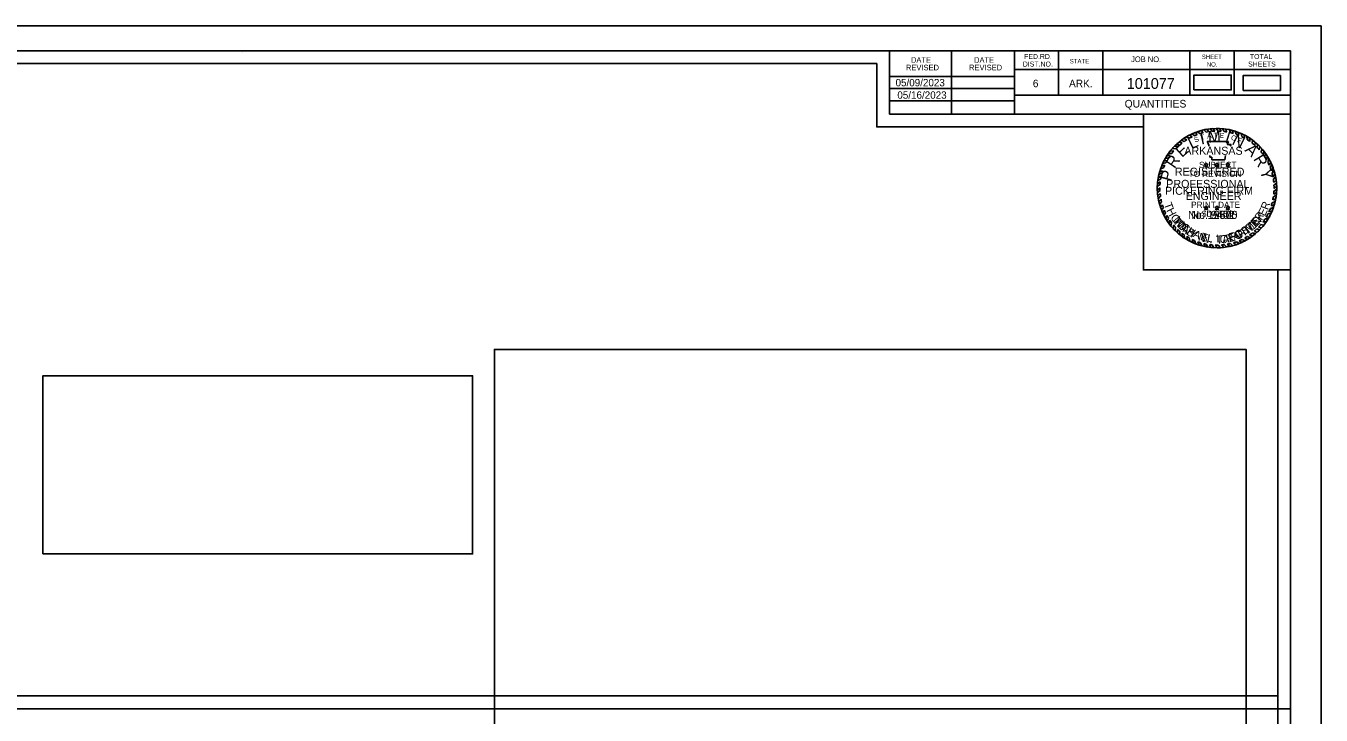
# Model space of a CAD drawing. Extents: x 1369655 to 1370989, y 380216 to 380430.
# Drawn here: x 1370286.3 to 1370488.6, y 380322.1 to 380429.8 of the extents above; entities that cross this region are included whole.
import ezdxf

# ---------------------------------------------------------------- set-up
doc = ezdxf.new("R2010")
doc.units = 0
for name, color, linetype in [('Default', 7, 'Continuous'), ('R_Border', 7, 'Continuous'), ('R_Border Notes', 7, 'Continuous'), ('R_Border Plan-Plan', 7, 'Continuous'), ('R_No Plot', 7, 'Continuous'), ('R_Revision Date Text', 7, 'Continuous'), ('STAMP_PE_CRAFTON', 7, 'Continuous'), ('STAMP_PE_FOSTER', 7, 'Continuous'), ('STAMP_PE_SEAL-INFO', 7, 'Continuous'), ('STAMP_PE_TAEGTMEYER', 7, 'Continuous'), ('STAMP_PE_TXT', 7, 'Continuous'), ('STAMP_PRELIMINARY', 7, 'Continuous')]:
    doc.layers.add(name, color=color, linetype=linetype)

msp = doc.modelspace()

# ---------------------------------------------------------------- linework, layer by layer
at = {"layer": 'Default'}
for points in [[(1370468.73, 380419.77), (1370474.56, 380419.77), (1370474.56, 380422.08), (1370468.73, 380422.08)], [(1370476.41, 380419.69), (1370482.24, 380419.69), (1370482.24, 380422), (1370476.41, 380422)], [(1370359.47, 380256.61), (1370476.87, 380256.61), (1370476.87, 380379.23), (1370359.47, 380379.23)], [(1370288.98, 380347.31), (1370356.07, 380347.31), (1370356.07, 380375.14), (1370288.98, 380375.14)]]:
    msp.add_lwpolyline(points, close=True, dxfattribs=at)
at = {"layer": 'R_Border'}
for p, q in [((1370167.65, 380425.87), (1370483.83, 380425.87)), ((1370320.17, 380425.61), (1370320.17, 380425.61)), ((1370320.17, 380425.61), (1370320.17, 380425.61)), ((1370421.19, 380415.99), (1370421.19, 380425.87)), ((1370430.87, 380415.99), (1370430.87, 380425.87)), ((1370440.73, 380425.87), (1370440.73, 380415.99)), ((1370447.57, 380425.87), (1370447.57, 380418.93)), ((1370454.51, 380425.87), (1370454.51, 380418.93)), ((1370468.09, 380425.87), (1370468.09, 380418.93)), ((1370475.03, 380425.87), (1370475.03, 380418.93)), ((1370483.83, 380220.41), (1370483.83, 380425.87)), ((1370421.19, 380421.85), (1370440.73, 380421.85)), ((1370483.83, 380422.93), (1370440.73, 380422.93)), ((1370483.83, 380422.95), (1370483.83, 380422.95)), ((1370421.19, 380419.99), (1370440.73, 380419.99)), ((1370421.19, 380418.05), (1370440.73, 380418.05)), ((1370483.83, 380418.93), (1370440.73, 380418.93)), ((1370443.69, 380418.93), (1370483.83, 380418.93)), ((1370483.83, 380415.99), (1370421.19, 380415.99))]:
    msp.add_line(p, q, dxfattribs=at)
at = {"layer": 'R_Border Plan-Plan'}
msp.add_line((1370167.65, 380323.14), (1370483.83, 380323.14), dxfattribs=at)
at = {"layer": 'R_No Plot'}
for points in [[(1370155.25, 380429.76), (1370488.59, 380429.76), (1370488.59, 380216.42), (1370155.25, 380216.42)], [(1370481.83, 380325.14), (1370169.65, 380325.14), (1370169.65, 380423.87), (1370419.19, 380423.87), (1370419.19, 380413.99), (1370436.73, 380413.99), (1370460.83, 380413.99), (1370460.83, 380391.65), (1370481.83, 380391.65)], [(1370169.65, 380423.87), (1370419.19, 380423.87), (1370419.19, 380413.99), (1370436.73, 380413.99), (1370460.83, 380413.99), (1370460.83, 380391.65), (1370481.83, 380391.65), (1370481.83, 380222.41), (1370169.65, 380222.41)], [(1370460.83, 380415.99), (1370483.83, 380415.99), (1370483.83, 380391.65), (1370460.83, 380391.65)]]:
    msp.add_lwpolyline(points, close=True, dxfattribs=at)
at = {"layer": 'STAMP_PE_SEAL-INFO'}
for p, q in [((1370468.95, 380413.12), (1370469.24, 380412.79)), ((1370469.29, 380413.24), (1370469.67, 380412.94)), ((1370469.88, 380413.43), (1370470.17, 380413.08)), ((1370470.27, 380413.52), (1370470.63, 380413.18)), ((1370470.75, 380413.62), (1370471.05, 380413.25)), ((1370471.27, 380413.69), (1370471.55, 380413.31)), ((1370472.01, 380413.34), (1370471.69, 380413.73)), ((1370472.5, 380413.34), (1370472.22, 380413.75)), ((1370472.96, 380413.32), (1370472.7, 380413.75)), ((1370473.47, 380413.27), (1370473.18, 380413.71)), ((1370473.89, 380413.21), (1370473.64, 380413.66)), ((1370474.46, 380413.09), (1370474.28, 380413.55)), ((1370474.86, 380412.98), (1370474.7, 380413.45)), ((1370475.31, 380412.83), (1370475.17, 380413.31)), ((1370475.73, 380412.67), (1370475.58, 380413.17)), ((1370466.03, 380411.3), (1370466.49, 380411.16)), ((1370466.37, 380411.6), (1370466.9, 380411.5)), ((1370466.75, 380411.93), (1370467.21, 380411.72)), ((1370467.17, 380412.19), (1370467.61, 380411.99)), ((1370467.56, 380412.44), (1370467.99, 380412.21)), ((1370468.01, 380412.69), (1370468.47, 380412.46)), ((1370468.44, 380412.9), (1370468.83, 380412.62)), ((1370470.81, 380411.72), (1370474.15, 380411.72)), ((1370470.93, 380411.41), (1370470.81, 380411.72)), ((1370471.03, 380411.12), (1370470.93, 380411.41)), ((1370471.04, 380411), (1370471.03, 380411.12)), ((1370474.15, 380411.72), (1370473.93, 380411.23)), ((1370473.93, 380411.23), (1370474.56, 380411.23)), ((1370474.56, 380411.23), (1370474.41, 380411)), ((1370476.19, 380412.47), (1370476.09, 380412.96)), ((1370476.63, 380412.24), (1370476.55, 380412.75)), ((1370477.02, 380412.01), (1370476.98, 380412.51)), ((1370477.46, 380411.72), (1370477.42, 380412.24)), ((1370477.82, 380411.46), (1370477.85, 380411.94)), ((1370478.26, 380411.09), (1370478.28, 380411.61)), ((1370478.58, 380410.79), (1370478.65, 380411.29)), ((1370464.27, 380409.11), (1370464.76, 380409.13)), ((1370464.51, 380409.51), (1370465.03, 380409.54)), ((1370464.75, 380409.85), (1370465.25, 380409.85)), ((1370465.03, 380410.22), (1370465.58, 380410.24)), ((1370465.37, 380410.63), (1370465.89, 380410.59)), ((1370465.7, 380410.98), (1370466.24, 380410.93)), ((1370471.23, 380409.29), (1370471.2, 380409.51)), ((1370471.54, 380409.29), (1370471.23, 380409.29)), ((1370471.54, 380408.86), (1370471.54, 380409.29)), ((1370473.59, 380409.2), (1370473.57, 380408.86)), ((1370473.67, 380409.51), (1370473.59, 380409.2)), ((1370478.93, 380410.42), (1370479, 380410.95)), ((1370479.21, 380410.1), (1370479.35, 380410.57)), ((1370479.53, 380409.69), (1370479.67, 380410.19)), ((1370479.75, 380409.37), (1370479.93, 380409.83)), ((1370480.06, 380408.87), (1370480.24, 380409.36)), ((1370463.36, 380406.95), (1370463.84, 380407.12)), ((1370463.52, 380407.45), (1370464, 380407.59)), ((1370463.67, 380407.86), (1370464.17, 380408.01)), ((1370463.85, 380408.29), (1370464.35, 380408.4)), ((1370464.04, 380408.68), (1370464.54, 380408.75)), ((1370473.57, 380408.86), (1370471.54, 380408.86)), ((1370480.26, 380408.51), (1370480.49, 380408.95)), ((1370480.49, 380408.02), (1370480.72, 380408.51)), ((1370480.63, 380407.69), (1370480.9, 380408.12)), ((1370480.83, 380407.14), (1370481.1, 380407.61)), ((1370480.93, 380406.77), (1370481.23, 380407.22)), ((1370463.44, 380404.98), (1370463.02, 380404.72)), ((1370463.47, 380405.4), (1370463.04, 380405.12)), ((1370463.53, 380405.84), (1370463.09, 380405.62)), ((1370463.62, 380406.3), (1370463.15, 380406.05)), ((1370463.25, 380406.54), (1370463.72, 380406.74)), ((1370481.07, 380406.21), (1370481.39, 380406.66)), ((1370481.14, 380405.83), (1370481.49, 380406.19)), ((1370481.2, 380405.32), (1370481.57, 380405.66)), ((1370481.23, 380404.91), (1370481.62, 380405.2)), ((1370463.42, 380404.49), (1370463.02, 380404.15)), ((1370463.43, 380404.08), (1370463.04, 380403.75)), ((1370463.46, 380403.58), (1370463.09, 380403.23)), ((1370463.51, 380403.15), (1370463.16, 380402.78)), ((1370481.15, 380403.09), (1370481.59, 380403.31)), ((1370481.2, 380403.48), (1370481.63, 380403.73)), ((1370481.24, 380403.98), (1370481.66, 380404.26)), ((1370481.25, 380404.39), (1370481.65, 380404.71)), ((1370463.59, 380402.69), (1370463.25, 380402.33)), ((1370463.68, 380402.28), (1370463.37, 380401.86)), ((1370463.81, 380401.83), (1370463.51, 380401.41)), ((1370463.95, 380401.41), (1370463.67, 380400.99)), ((1370464.12, 380400.98), (1370463.85, 380400.56)), ((1370480.67, 380401.26), (1370481.15, 380401.39)), ((1370480.8, 380401.64), (1370481.29, 380401.84)), ((1370480.95, 380402.14), (1370481.42, 380402.34)), ((1370481.06, 380402.59), (1370481.51, 380402.78)), ((1370464.29, 380400.6), (1370464.06, 380400.13)), ((1370464.52, 380400.14), (1370464.33, 380399.65)), ((1370464.76, 380399.73), (1370464.57, 380399.26)), ((1370464.96, 380399.42), (1370464.85, 380398.87)), ((1370465.24, 380399.03), (1370465.14, 380398.5)), ((1370479.51, 380399.14), (1370480.01, 380399.14)), ((1370479.85, 380399.63), (1370480.32, 380399.63)), ((1370480.02, 380399.91), (1370480.52, 380399.97)), ((1370480.29, 380400.41), (1370480.78, 380400.48)), ((1370480.45, 380400.75), (1370480.94, 380400.84)), ((1370465.54, 380398.65), (1370465.46, 380398.13)), ((1370465.85, 380398.32), (1370465.79, 380397.79)), ((1370466.17, 380397.99), (1370466.14, 380397.46)), ((1370466.51, 380397.68), (1370466.51, 380397.15)), ((1370466.87, 380397.38), (1370466.89, 380396.86)), ((1370467.21, 380397.13), (1370467.25, 380396.62)), ((1370477.08, 380396.89), (1370477.53, 380396.69)), ((1370477.42, 380397.11), (1370477.86, 380396.92)), ((1370477.88, 380397.46), (1370478.35, 380397.31)), ((1370478.16, 380397.68), (1370478.63, 380397.55)), ((1370478.56, 380398.05), (1370479, 380397.91)), ((1370478.82, 380398.31), (1370479.29, 380398.23)), ((1370479.2, 380398.74), (1370479.66, 380398.67)), ((1370467.64, 380396.85), (1370467.7, 380396.34)), ((1370467.99, 380396.65), (1370468.08, 380396.13)), ((1370468.47, 380396.4), (1370468.63, 380395.88)), ((1370468.84, 380396.23), (1370469.02, 380395.72)), ((1370469.34, 380396.04), (1370469.55, 380395.53)), ((1370469.75, 380395.9), (1370469.97, 380395.41)), ((1370470.25, 380395.76), (1370470.47, 380395.3)), ((1370470.65, 380395.68), (1370470.9, 380395.22)), ((1370471.15, 380395.6), (1370471.39, 380395.16)), ((1370471.59, 380395.55), (1370471.86, 380395.12)), ((1370472.07, 380395.52), (1370472.38, 380395.11)), ((1370472.53, 380395.52), (1370472.88, 380395.12)), ((1370473.05, 380395.55), (1370473.38, 380395.17)), ((1370473.49, 380395.59), (1370473.86, 380395.23)), ((1370473.93, 380395.66), (1370474.32, 380395.32)), ((1370474.43, 380395.77), (1370474.8, 380395.44)), ((1370474.89, 380395.89), (1370475.3, 380395.59)), ((1370475.38, 380396.05), (1370475.82, 380395.78)), ((1370475.8, 380396.22), (1370476.22, 380395.96)), ((1370476.26, 380396.43), (1370476.74, 380396.22)), ((1370476.67, 380396.64), (1370477.08, 380396.41))]:
    msp.add_line(p, q, dxfattribs=at)
for radius, start, end in [(9.32, 111.3124, 114.7026), (9.32, 105.2339, 109.0352), (8.91, 104.0352, 107.3615), (9.32, 99.7525, 102.7765), (8.91, 98.258, 101.0329), (9.32, 93.9381, 96.5517), (8.91, 92.1102, 95.0367), (9.32, 87.7298, 90.6707), (8.91, 85.9628, 88.9097), (9.32, 81.9732, 84.8236), (8.91, 79.9264, 82.696), (9.32, 75.3125, 77.9426), (8.91, 73.5575, 76.2314), (9.32, 69.6061, 72.3058), (9.32, 129.7326, 132.5376), (8.91, 127.5297, 130.9683), (9.32, 123.6199, 126.5906), (8.91, 121.9746, 125.11), (9.32, 117.6544, 120.8099), (8.91, 115.6869, 119.1583), (8.91, 110.3086, 113.1659), (8.91, 67.6248, 70.504), (9.32, 63.1329, 66.2704), (8.91, 61.1558, 64.3784), (9.32, 56.9003, 60.0942), (8.91, 54.9238, 58.2702), (8.91, 48.3016, 52.0395), (9.32, 50.3492, 53.7159), (9.32, 44.3405, 47.3929), (9.32, 147.0072, 149.899), (9.32, 141.6056, 144.4486), (8.91, 145.0197, 148.2104), (8.91, 139.301, 142.5873), (9.32, 135.4021, 138.3031), (8.91, 133.1331, 136.2562), (8.91, 42.2212, 45.5512), (8.91, 36.135, 39.5311), (9.32, 38.1247, 41.2316), (8.91, 29.9032, 33.6645), (9.32, 31.9614, 35.4294), (9.32, 158.4077, 161.0701), (8.91, 162.4331, 165.0013), (9.32, 152.864, 155.5189), (8.91, 156.3402, 159.2319), (8.91, 151.0315, 153.573), (8.91, 23.7732, 27.2211), (9.32, 25.9391, 29.0125), (8.91, 17.6802, 21.4251), (9.32, 19.9538, 23.3141), (9.32, 13.8421, 17.4447), (9.32, 175.7409, 178.2066), (9.32, 170.0003, 172.6878), (9.32, 164.3068, 166.894), (8.91, 173.73, 176.4734), (8.91, 167.9048, 170.9039), (8.91, 11.5444, 15.2364), (8.91, 5.7599, 9.0606), (9.32, 7.5852, 10.8621), (9.32, 1.7215, 4.7268), (9.32, 181.7251, 184.1626), (9.32, 187.4204, 190.1927), (8.91, 179.6454, 182.2633), (8.91, 185.4539, 188.234), (8.91, 348.0778, 351.3435), (8.91, 353.8632, 357.1274), (8.91, 359.7329, 3.0639), (9.32, 349.8305, 353.0885), (9.32, 355.7156, 358.9569), (9.32, 193.0369, 195.9973), (9.32, 198.8967, 201.6281), (8.91, 191.2274, 193.9858), (8.91, 196.9675, 199.8353), (8.91, 202.7761, 205.4791), (8.91, 335.6038, 339.1858), (8.91, 341.777, 345.0925), (9.32, 337.3837, 340.9933), (9.32, 343.8925, 347.035), (9.32, 204.5479, 207.4328), (9.32, 210.8636, 213.6571), (8.91, 208.7883, 211.7934), (8.91, 214.1838, 217.2747), (8.91, 323.5851, 327.4407), (9.32, 325.4405, 328.9872), (8.91, 329.5549, 333.2076), (9.32, 331.4037, 334.9332), (9.32, 216.6115, 219.491), (9.32, 222.48, 225.3801), (8.91, 220.3909, 223.3056), (9.32, 228.3665, 231.348), (8.91, 226.2494, 229.2407), (8.91, 232.229, 234.9336), (8.91, 299.0768, 302.1724), (8.91, 304.823, 308.5143), (9.32, 306.3721, 310.208), (8.91, 310.7744, 314.3161), (9.32, 312.4518, 315.6633), (8.91, 316.6531, 320.3711), (9.32, 318.2846, 321.8043), (9.32, 234.295, 236.9452), (8.91, 238.2223, 240.8353), (9.32, 240.1977, 242.8613), (8.91, 244.3204, 246.9486), (9.32, 246.576, 249.1558), (8.91, 250.3491, 253.1216), (9.32, 252.5967, 255.3252), (8.91, 256.505, 259.1192), (9.32, 258.4433, 261.1398), (8.91, 262.3783, 265.2012), (9.32, 264.1978, 267.1009), (8.91, 268.3215, 271.277), (9.32, 270.2548, 273.3361), (8.91, 274.6157, 277.4486), (9.32, 276.4239, 279.4357), (8.91, 280.3459, 283.5814), (9.32, 282.3199, 285.3702), (8.91, 286.6423, 289.9783), (9.32, 288.5709, 291.9733), (8.91, 292.8745, 296.1185), (9.32, 294.6481, 298.2166), (9.32, 300.621, 303.8703)]:
    msp.add_arc((1370472.33, 380404.43), radius, start, end, dxfattribs=at)
at = {"layer": 'STAMP_PE_TXT'}
for p, q in [((1370470.51, 380408), (1370470.31, 380408.15)), ((1370470.31, 380408.15), (1370470.56, 380408.15)), ((1370470.44, 380407.77), (1370470.51, 380408)), ((1370470.64, 380407.91), (1370470.44, 380407.77)), ((1370470.56, 380408.15), (1370470.64, 380408.38)), ((1370470.64, 380408.38), (1370470.71, 380408.15)), ((1370470.83, 380407.77), (1370470.64, 380407.91)), ((1370470.71, 380408.15), (1370470.96, 380408.15)), ((1370470.96, 380408.15), (1370470.76, 380408)), ((1370470.76, 380408), (1370470.83, 380407.77)), ((1370472.21, 380408), (1370472.01, 380408.15)), ((1370472.01, 380408.15), (1370472.26, 380408.15)), ((1370472.14, 380407.77), (1370472.21, 380408)), ((1370472.33, 380407.91), (1370472.14, 380407.77)), ((1370472.26, 380408.15), (1370472.33, 380408.38)), ((1370472.33, 380408.38), (1370472.41, 380408.15)), ((1370472.53, 380407.77), (1370472.33, 380407.91)), ((1370472.41, 380408.15), (1370472.65, 380408.15)), ((1370472.65, 380408.15), (1370472.46, 380408)), ((1370472.46, 380408), (1370472.53, 380407.77)), ((1370473.91, 380408), (1370473.71, 380408.15)), ((1370473.71, 380408.15), (1370473.96, 380408.15)), ((1370473.83, 380407.77), (1370473.91, 380408)), ((1370474.03, 380407.91), (1370473.83, 380407.77)), ((1370473.96, 380408.15), (1370474.03, 380408.38)), ((1370474.03, 380408.38), (1370474.11, 380408.15)), ((1370474.23, 380407.77), (1370474.03, 380407.91)), ((1370474.11, 380408.15), (1370474.35, 380408.15)), ((1370474.35, 380408.15), (1370474.15, 380408)), ((1370474.15, 380408), (1370474.23, 380407.77)), ((1370470.51, 380401.29), (1370470.31, 380401.44)), ((1370470.31, 380401.44), (1370470.56, 380401.44)), ((1370470.44, 380401.06), (1370470.51, 380401.29)), ((1370470.64, 380401.21), (1370470.44, 380401.06)), ((1370470.56, 380401.44), (1370470.64, 380401.67)), ((1370470.64, 380401.67), (1370470.71, 380401.44)), ((1370470.83, 380401.06), (1370470.64, 380401.21)), ((1370470.71, 380401.44), (1370470.96, 380401.44)), ((1370470.96, 380401.44), (1370470.76, 380401.29)), ((1370470.76, 380401.29), (1370470.83, 380401.06)), ((1370472.21, 380401.29), (1370472.01, 380401.44)), ((1370472.01, 380401.44), (1370472.26, 380401.44)), ((1370472.14, 380401.06), (1370472.21, 380401.29)), ((1370472.33, 380401.21), (1370472.14, 380401.06)), ((1370472.26, 380401.44), (1370472.33, 380401.67)), ((1370472.33, 380401.67), (1370472.41, 380401.44)), ((1370472.53, 380401.06), (1370472.33, 380401.21)), ((1370472.41, 380401.44), (1370472.65, 380401.44)), ((1370472.65, 380401.44), (1370472.46, 380401.29)), ((1370472.46, 380401.29), (1370472.53, 380401.06)), ((1370473.91, 380401.29), (1370473.71, 380401.44)), ((1370473.71, 380401.44), (1370473.96, 380401.44)), ((1370473.83, 380401.06), (1370473.91, 380401.29)), ((1370474.03, 380401.21), (1370473.83, 380401.06)), ((1370473.96, 380401.44), (1370474.03, 380401.67)), ((1370474.03, 380401.67), (1370474.11, 380401.44)), ((1370474.23, 380401.06), (1370474.03, 380401.21)), ((1370474.11, 380401.44), (1370474.35, 380401.44)), ((1370474.35, 380401.44), (1370474.15, 380401.29)), ((1370474.15, 380401.29), (1370474.23, 380401.06))]:
    msp.add_line(p, q, dxfattribs=at)
at = {"layer": 'STAMP_PRELIMINARY'}
msp.add_circle((1370472.33, 380404.43), 9.32, dxfattribs=at)

# ---------------------------------------------------------------- texts
at = {"layer": 'R_Border'}
for s, height, p in [('FED.RD.', 0.782, (1370442.21, 380424.59)), ('SHEET', 0.684, (1370469.95, 380424.59)), ('TOTAL', 0.782, (1370477.47, 380424.59)), ('REVISED', 0.879, (1370423.75, 380422.82)), ('DATE', 0.879, (1370424.53, 380424)), ('REVISED', 0.879, (1370433.61, 380422.82)), ('DATE', 0.879, (1370434.39, 380424)), ('DIST.NO.', 0.782, (1370442.01, 380423.41)), ('STATE', 0.684, (1370449.33, 380423.91)), ('JOB NO.', 0.879, (1370458.91, 380424.11)), ('NO.', 0.684, (1370470.73, 380423.41)), ('SHEETS', 0.782, (1370477.19, 380423.41)), ('6', 1.17, (1370443.57, 380420.19)), ('ARK.', 1.172, (1370449.23, 380420.19))]:
    msp.add_text(s, height=height, dxfattribs=at).set_placement(p)
at = {"layer": 'R_Border Notes'}
for s, height, p in [('101077', 1.68, (1370458.24, 380419.93)), ('QUANTITIES', 1.2, (1370457.91, 380417.01))]:
    msp.add_text(s, height=height, dxfattribs=at).set_placement(p)
at = {"layer": 'R_Revision Date Text'}
for s, p in [('05/09/2023', (1370422.13, 380420.33)), ('05/16/2023', (1370422.41, 380418.39))]:
    msp.add_text(s, height=1.15, dxfattribs=at).set_placement(p)
at = {"layer": 'STAMP_PE_CRAFTON'}
for s, rotation, p in [('T', 310.7442, (1370465.3, 380399.33)), ('O', 317.6422, (1370465.97, 380398.52)), ('O', 41.8391, (1370477.77, 380397.67)), ('N', 49.2411, (1370478.62, 380398.45)), ('N', 324.4537, (1370466.81, 380397.73)), ('Y', 331.1686, (1370467.85, 380397.02)), ('N', 347.4752, (1370469.9, 380396.1)), ('C', 6.0117, (1370472.81, 380395.77)), ('R', 14.8189, (1370473.9, 380395.89)), ('A', 20.5125, (1370475.01, 380396.19)), ('F', 28.7821, (1370475.99, 380396.56)), ('T', 34.1136, (1370476.91, 380397.07)), ('.', 356.8926, (1370471.13, 380395.82))]:
    msp.add_text(s, height=1.25, rotation=rotation, dxfattribs=at).set_placement(p)
msp.add_text('No. 12370', height=1.25, dxfattribs=at).set_placement((1370467.8, 380399.63))
at = {"layer": 'STAMP_PE_FOSTER'}
for s, rotation, p in [('M', 308.339, (1370465.45, 380399.45)), ('I', 314.1842, (1370466.25, 380398.51)), ('T', 39.4194, (1370477.48, 380397.67)), ('E', 46.9613, (1370478.33, 380398.42)), ('R', 54.5031, (1370479.06, 380399.24)), ('C', 319.8733, (1370466.6, 380398.16)), ('H', 327.7235, (1370467.53, 380397.42)), ('A', 335.7276, (1370468.51, 380396.84)), ('E', 343.5779, (1370469.65, 380396.37)), ('L', 350.8115, (1370470.71, 380396.1)), ('L', 1.2666, (1370472.25, 380395.94)), ('F', 15.8691, (1370474.37, 380396.18)), ('O', 23.719, (1370475.41, 380396.51)), ('S', 31.7234, (1370476.52, 380397.04)), ('.', 6.8035, (1370473.29, 380396))]:
    msp.add_text(s, height=1.2, rotation=rotation, dxfattribs=at).set_placement(p)
msp.add_text('No. 9402', height=1.25, dxfattribs=at).set_placement((1370468.32, 380399.63))
at = {"layer": 'STAMP_PE_TAEGTMEYER'}
for s, rotation, p in [('T', 289.646, (1370464.03, 380401.94)), ('H', 296.7339, (1370464.39, 380400.96)), ('E', 63.0984, (1370479.78, 380399.96)), ('R', 69.57, (1370480.28, 380400.94)), ('O', 303.7708, (1370464.98, 380399.85)), ('M', 314.2033, (1370465.64, 380398.9)), ('M', 39.3, (1370477.33, 380397.33)), ('E', 46.8094, (1370478.37, 380398.21)), ('Y', 53.9986, (1370479.11, 380399.02)), ('A', 321.0594, (1370466.6, 380397.93)), ('S', 327.8239, (1370467.42, 380397.29)), ('N', 344.2727, (1370469.32, 380396.28)), ('T', 3.0061, (1370472.2, 380395.75)), ('A', 8.9826, (1370473.24, 380395.81)), ('E', 17.6836, (1370474.28, 380395.96)), ('G', 23.3052, (1370475.33, 380396.29)), ('T', 31.466, (1370476.43, 380396.78)), ('.', 350.6464, (1370470.53, 380395.95))]:
    msp.add_text(s, height=1.25, rotation=rotation, dxfattribs=at).set_placement(p)
msp.add_text('No. 19605', height=1.25, dxfattribs=at).set_placement((1370467.8, 380399.63))
at = {"layer": 'STAMP_PE_TXT'}
for s, rotation, p in [('T', 1.8248, (1370471.8, 380412.29)), ('E', 355.2002, (1370472.71, 380412.3)), ('S', 23.5541, (1370468.93, 380411.53)), ('T', 16.311, (1370469.86, 380411.91)), ('A', 9.0679, (1370470.82, 380412.16)), ('O', 342.2506, (1370474.44, 380412.02)), ('F', 335.0075, (1370475.41, 380411.68))]:
    msp.add_text(s, height=0.781, rotation=rotation, dxfattribs=at).set_placement(p)
for s, p in [('ARKANSAS', (1370467.23, 380409.64)), ('REGISTERED', (1370465.75, 380406.37)), ('PROFESSIONAL', (1370464.4, 380404.47)), ('ENGINEER', (1370467.44, 380402.57))]:
    msp.add_text(s, height=1.25, dxfattribs=at).set_placement(p)
at = {"layer": 'STAMP_PRELIMINARY'}
for s, rotation, p in [('I', 12.5248, (1370469.87, 380411.22)), ('M', 3.1074, (1370470.97, 380411.53)), ('I', 342.3164, (1370473.44, 380411.59)), ('E', 42.3578, (1370466.86, 380409.13)), ('L', 25.513, (1370468.34, 380410.46)), ('N', 333.9382, (1370474.54, 380411.32)), ('A', 315.6579, (1370476.58, 380410.29)), ('R', 56.2292, (1370465.7, 380407.39)), ('R', 301.3831, (1370477.95, 380408.98)), ('P', 73.913, (1370465.16, 380405.37)), ('Y', 283.2593, (1370479.04, 380407.19))]:
    msp.add_text(s, height=1.8, rotation=rotation, dxfattribs=at).set_placement(p)
for s, height, p in [('TO REVISION', 0.96, (1370467.87, 380406.19)), ('SUBJECT', 0.96, (1370469.53, 380407.58)), ('PICKERING FIRM', 1.25, (1370464.21, 380403.39)), ('PRINT DATE', 0.96, (1370468.29, 380401.35)), ('$DATE$', 0.96, (1370469.97, 380399.96))]:
    msp.add_text(s, height=height, dxfattribs=at).set_placement(p)

doc.saveas('drawing.dxf')
